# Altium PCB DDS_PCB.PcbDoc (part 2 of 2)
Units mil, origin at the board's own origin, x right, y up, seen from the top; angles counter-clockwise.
Board outline 3998.07 x 3476.44 mil, 8 copper layers (TOP_L1, Plane_L2, Inner_L3, Plane_L4, Plane_L5, Inner_L6, Plane_L7, Bottom Layer_L8), stack 26.8 mil thick; 404 components, 274 nets, 1325 pads, 24 vias.
Unrouted connection lines stored in the file: 923.
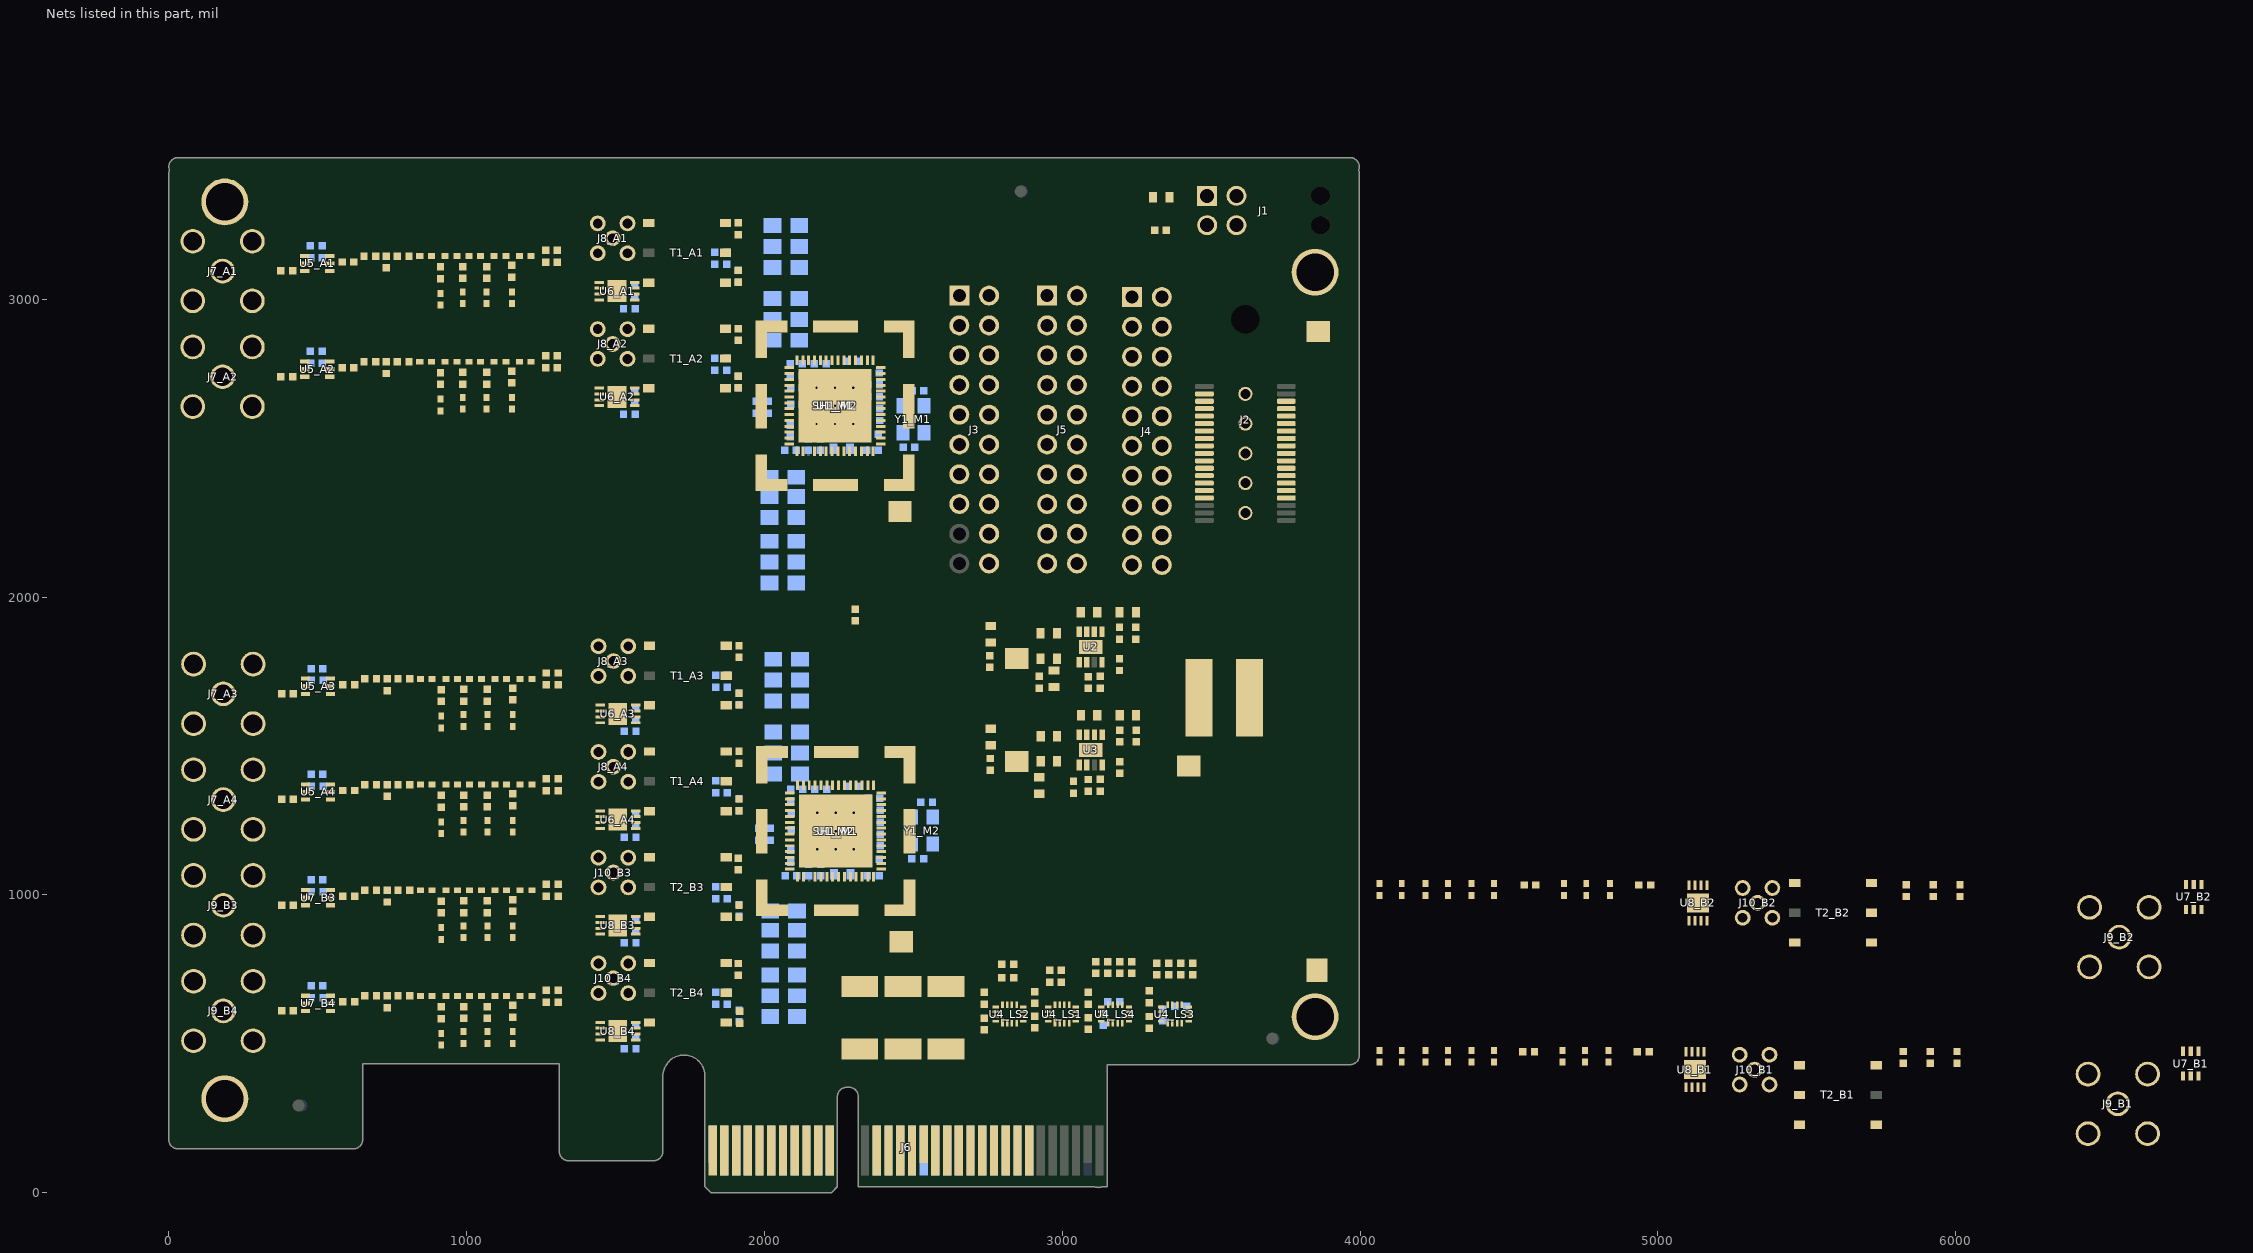
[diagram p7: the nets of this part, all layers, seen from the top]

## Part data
C1_M1 C1_M2: library part "CAP CER 6.8pF 50V NP0 0402", "CAP CER 680PF 50V NP0 0402", Capacitance=680pF, Manufacturer="TDK Corporation", Manufacturer Part Number=C1005C0G1H6R8D, Package / Case="0402 (1005 Metric)", Voltage - Rated=50V
C2_M1 C2_M2 C3_M1 C3_M2: library part "CAP CER 6.8pF 50V NP0 0402", "CAP CER 39PF 50V NP0 0402", Capacitance=39pF, Manufacturer="TDK Corporation", Manufacturer Part Number=C1005C0G1H6R8D, Package / Case="0402 (1005 Metric)", Voltage - Rated=50V
C4_M1 C4_M2 C5_M1 C5_M2 C6_M1 C6_M2 C31_A1 C31_A2 C31_A3 C31_A4 C32_A1 C32_A2 C32_A3 C32_A4 C37_A1 C37_A2 C37_A3 C37_A4 C40_A1 C40_A2 C40_A3 C40_A4 C44_B3 C44_B4 C45_B3 C45_B4 C50_B3 C50_B4 C53_B3 C53_B4: library part "CAP CER 6.8pF 50V NP0 0402", "CAP CER 1uF 25V X5R 0402", Capacitance=1uF, Manufacturer="TDK Corporation", Manufacturer Part Number=C1005C0G1H6R8D, Package / Case="0402 (1005 Metric)", Voltage - Rated=50V
C7_M1 C7_M2 C8_M1 C8_M2 C9_M1 C9_M2 C43_A1 C43_A2 C43_A3 C43_A4 C56_B3 C56_B4: library part "CAP CER 6.8pF 50V NP0 0402", "CAP CER 10uF 10V X5R 0402", Capacitance=10uF, Manufacturer="TDK Corporation", Manufacturer Part Number=C1005C0G1H6R8D, Package / Case="0402 (1005 Metric)", Voltage - Rated=50V
C10_M1 C10_M2 C11_M1 C11_M2 C12_M1 C12_M2 C29_LS1 C29_LS2 C29_LS3 C29_LS4 C30_LS1 C30_LS2 C30_LS3 C30_LS4 C38_A1 C38_A2 C38_A3 C38_A4 C39_A1 C39_A2 C39_A3 C39_A4 C41_A1 C41_A2 C41_A3 C41_A4 C42_A1 C42_A2 C42_A3 C42_A4 C51_B3 C51_B4 C52_B3 C52_B4 C54_B3 C54_B4 C55_B3 C55_B4: library part "CAP CER 6.8pF 50V NP0 0402", "CAP CER 0.1uF 50V NP0 0402", Capacitance=0.1uF, Manufacturer="TDK Corporation", Manufacturer Part Number=C1005C0G1H6R8D, Package / Case="0402 (1005 Metric)", Voltage - Rated=50V
C13 C20 C26: library part "CAP CER 10uF 10V 10% X5R 0603", "CAP CER 10UF 25V 10% X5R 0603", Capacitance=10µF, Manufacturer="TDK Corporation", Manufacturer Part Number=C1608X5R1A106K, Package / Case="0603 (1608 Metric)", Voltage - Rated=10V
C14 C15 C18 C19 C22 C24 C25: library part "CAP CER 12nF 25V 10% X7R 0402", "CAP CER 10nF 25V 10% X5R 0402", Capacitance=10nF, Manufacturer="Murata Electronics North America", Manufacturer Part Number=GRM155R71E123KA61D, Package / Case="0402 (1005 Metric)", Voltage - Rated=25V
C16 C17 C23 C27: library part "CAP CER 10uF 10V 10% X5R 0603", "CAP CER 22UF 16V 10% X5R 0603", Capacitance=22µF, Manufacturer="TDK Corporation", Manufacturer Part Number=C1608X5R1A106K, Package / Case="0603 (1608 Metric)", Voltage - Rated=10V
C21 C28: library part "CAP CER 6.8pF 50V NP0 0402", "CAP CER NA 50V NP0 0402", Manufacturer="TDK Corporation", Manufacturer Part Number=C1005C0G1H6R8D, Package / Case="0402 (1005 Metric)", Voltage - Rated=50V
C33_A1 C33_A2 C33_A3 C33_A4 C46_B3 C46_B4: library part "CAP CER 20pF 50V 5% NP0 0402", "CAP CER 16PF 50V 5% NP0 0402", Capacitance=16pF, Manufacturer="TDK Corporation", Manufacturer Part Number=C1005C0G1H200J, Package / Case="0402 (1005 Metric)", Voltage - Rated=50V
C34_A1 C34_A2 C34_A3 C34_A4 C47_B3 C47_B4: library part "CAP CER 20pF 50V 5% NP0 0402", "CAP CER 11PF 50V 5% NP0 0402", Capacitance=11pF, Manufacturer="TDK Corporation", Manufacturer Part Number=C1005C0G1H200J, Package / Case="0402 (1005 Metric)", Voltage - Rated=50V
C35_A1 C35_A2 C35_A3 C35_A4 C48_B3 C48_B4: library part "CAP CER 20pF 50V 5% NP0 0402", "CAP CER 10PF 50V 5% NP0 0402", Capacitance=10pF, Manufacturer="TDK Corporation", Manufacturer Part Number=C1005C0G1H200J, Package / Case="0402 (1005 Metric)", Voltage - Rated=50V
C36_A1 C36_A2 C36_A3 C36_A4 C49_B3 C49_B4: library part "CAP CER 20pF 50V 5% NP0 0402", "CAP CER 13PF 50V 5% NP0 0402", Capacitance=13pF, Manufacturer="TDK Corporation", Manufacturer Part Number=C1005C0G1H200J, Package / Case="0402 (1005 Metric)", Voltage - Rated=50V
F1 F2 F3: library part 1812L150/24MR, "FUSE PTC 24V 1.5A POLYFUSE 1812", Current - Hold (Ih) (Max)=1.5A, Manufacturer="Littelfuse Inc", Package / Case="1812 (4532 Metric), Concave"
FB1_M1 FB1_M2 FB2 FB3 FB4 FB5: library part BK1608HS600-T, "FERRITE BEAD 220_OHM@100MHz 0603 2A 50mohm_DC", Manufacturer="Taiyo Yuden", Package / Case="0603 (1608 Metric)"
H1 H2 H3 H4: "hole 3mm"
J1: "No Description Available", Mfr_Name="Molex Connector Corporation"
J2: "CONN MICTOR 38POS .025 VERT SMD", Manufacturer="TE Connectivity"
J3 J4 J5: "CONN HEADER 20 TH", Manufacturer="Molex Connector Corporation"
J6: "64 Position Female Connector PCI Expressâ„¢ Gold 0.039 _1.00mm_ Black", Package=None
J7_A1 J7_A2 J7_A3 J7_A4 J9_B1 J9_B2 J9_B3 J9_B4: "No Description Available", Mfr_Name="Samtec Inc"
J8_A1 J8_A2 J8_A3 J8_A4 J10_B1 J10_B2 J10_B3 J10_B4: "MMCX STRAIGHT, THROUGH HOLE JACK- 50 OHM", Package=None
LD1 LD2: "LED 1.6X0.8MM 568NM GRN CLR SMD", Manufacturer="Kingbright Corp", Package / Case="0603 (1608 Metric)"
Lp1: "INDUCTOR 10UH 1.9A 20% SMD", Manufacturer="Taiyo Yuden", Package / Case="Non Standard"
R1_M1 R1_M2: library part "RES 3.09K OHM 1/16W 1% 0402", "RES 6.8K OHM 1/16W 1% 0402", Manufacturer="Stackpole Electronics Inc", Manufacturer Part Number=RMCF0402FT3K09, Package / Case="0402 (1005 Metric)", Power (Watts)="0.063W, 1/16W", Supplier Device Package=0402
R2_M1 R2_M2 R7_M1 R7_M2 R8_M1 R8_M2 R9_M1 R9_M2 R10_M1 R10_M2 R33 R41_A1 R41_A2 R41_A3 R41_A4 R42_A1 R42_A2 R42_A3 R42_A4 R48_B1 R48_B2 R48_B3 R48_B4 R49_B1 R49_B2 R49_B3 R49_B4: library part "RES 100 OHM 1/10W 1% 0402 SMD", "RES 0 OHM 1/10W 1% 0402 SMD", Manufacturer="Panasonic Electronic Components", Manufacturer Part Number=ERJ-2RKF1000X, Package / Case="0402 (1005 Metric)", Supplier Device Package=0402
R3_M1 R3_M2 R4_M1 R4_M2 R5_M1 R5_M2 R6_M1 R6_M2 R11_M1 R11_M2 R12_M1 R12_M2 R13_M1 R13_M2 R14_M1 R14_M2: library part "RES 3.09K OHM 1/16W 1% 0402", "RES 10K OHM 1/16W 1% 0402", Manufacturer="Stackpole Electronics Inc", Manufacturer Part Number=RMCF0402FT3K09, Package / Case="0402 (1005 Metric)", Power (Watts)="0.063W, 1/16W", Supplier Device Package=0402
R15_M1 R15_M2 R16_M1 R16_M2 R17_M1 R17_M2 R18_M1 R18_M2 R19_M1 R19_M2 R20_M1 R20_M2 R21_M1 R21_M2 R22_M1 R22_M2 R23_M1 R23_M2 R24_M1 R24_M2 R25_M1 R25_M2 R26_M1 R26_M2: library part "RES 200 OHM 1/8W 1% 0805 SMD", "RES 0 OHM 1/8W 1% 0805 SMD", Manufacturer="Stackpole Electronics Inc", Manufacturer Part Number=RMCF0805FT200R, Package / Case="0805 (2012 Metric)", Power (Watts)="0.125W, 1/8W", Supplier Device Package=0805
R27 R30: library part "RES 15.4K OHM 1/10W 1% 0402 SMD", "RES 124K OHM 1/10W 1% 0402 SMD", Manufacturer="Panasonic Electronic Components", Manufacturer Part Number=ERJ-2RKF1542X, Package / Case="0402 (1005 Metric)", Power (Watts)="0.1W, 1/10W", Supplier Device Package=0402
R28 R31: library part "RES 3.09K OHM 1/16W 1% 0402", "RES 1K OHM 1/16W 1% 0402", Manufacturer="Stackpole Electronics Inc", Manufacturer Part Number=RMCF0402FT3K09, Package / Case="0402 (1005 Metric)", Power (Watts)="0.063W, 1/16W", Supplier Device Package=0402
R29: library part "RES 15.4K OHM 1/10W 1% 0402 SMD", "RES 39.2K OHM 1/10W 1% 0402 SMD", Manufacturer="Panasonic Electronic Components", Manufacturer Part Number=ERJ-2RKF1542X, Package / Case="0402 (1005 Metric)", Power (Watts)="0.1W, 1/10W", Supplier Device Package=0402
R32 R34_LS1 R34_LS2 R34_LS3 R34_LS4: library part "RES 3.09K OHM 1/16W 1% 0402", "RES 100K OHM 1/16W 1% 0402", Manufacturer="Stackpole Electronics Inc", Manufacturer Part Number=RMCF0402FT3K09, Package / Case="0402 (1005 Metric)", Power (Watts)="0.063W, 1/16W", Supplier Device Package=0402
R35_LS1 R35_LS2 R35_LS3 R35_LS4: library part "RES 3.09K OHM 1/16W 1% 0402", "RES 3.09K OHM 1/16W 1% 0402", Manufacturer="Stackpole Electronics Inc", Manufacturer Part Number=RMCF0402FT3K09, Package / Case="0402 (1005 Metric)", Power (Watts)="0.063W, 1/16W", Supplier Device Package=0402
R36_A1 R36_A2 R36_A3 R36_A4 R37_A1 R37_A2 R37_A3 R37_A4 R43_B1 R43_B2 R43_B3 R43_B4 R44_B1 R44_B2 R44_B3 R44_B4: library part "RES 100 OHM 1/10W 1% 0402 SMD", "RES 34.8 OHM 1/10W 1% 0402 SMD", Manufacturer="Panasonic Electronic Components", Manufacturer Part Number=ERJ-2RKF1000X, Package / Case="0402 (1005 Metric)", Supplier Device Package=0402
R38_A1 R38_A2 R38_A3 R38_A4 R45_B1 R45_B2 R45_B3 R45_B4: library part "RES 100 OHM 1/10W 1% 0402 SMD", "RES 18.2 OHM 1/10W 1% 0402 SMD", Manufacturer="Panasonic Electronic Components", Manufacturer Part Number=ERJ-2RKF1000X, Package / Case="0402 (1005 Metric)", Supplier Device Package=0402
R39_A1 R39_A2 R39_A3 R39_A4 R40_A1 R40_A2 R40_A3 R40_A4 R46_B3 R46_B4 R47_B3 R47_B4: library part "RES 100 OHM 1/10W 1% 0402 SMD", "RES 49.9 OHM 1/10W 1% 0402 SMD", Manufacturer="Panasonic Electronic Components", Manufacturer Part Number=ERJ-2RKF1000X, Package / Case="0402 (1005 Metric)", Supplier Device Package=0402
SH1_M1 SH1_M2: "RF SHIELD 0.5\" X 0.538\" SMD", Manufacturer="Leader Tech Inc.", Manufacturer_Part_Number=SMS-201F
T1_A1 T1_A2 T1_A3 T1_A4 T2_B1 T2_B2 T2_B3 T2_B4: "No Description Available", Mfr_Name="Mini Circuits"
TP1 TP2 TP3 TP4 TP5 TP6: library part "TP mini_2", "TP PC MINIATURE SMT", Manufacturer="Keystone Electronics", Manufacturer Part Number=5015
TP7: library part "TP mini_1", "TP PC MINIATURE SMT", Manufacturer="Keystone Electronics", Manufacturer Part Number=5015
U1_M1 U1_M2 U6_A1 U6_A2 U6_A3 U6_A4 U8_B1 U8_B2 U8_B3 U8_B4: "No Description Available", Mfr_Name="Analog Devices Inc"
U2 U3: "No Description Available", Mfr_Name=Delta
U5_A1 U5_A2 U5_A3 U5_A4 U7_B1 U7_B2 U7_B3 U7_B4: "No Description Available", Mfr_Name=NXP
Y1_M1 Y1_M2: "No Description Available", Mfr_Name="ECS International"

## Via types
v1: diameter 16, hole 8, TOP_L1 to Bottom Layer_L8, tented both sides, 18 vias
v2: diameter 25.59, hole 11.81, TOP_L1 to Bottom Layer_L8, tented both sides, 6 vias

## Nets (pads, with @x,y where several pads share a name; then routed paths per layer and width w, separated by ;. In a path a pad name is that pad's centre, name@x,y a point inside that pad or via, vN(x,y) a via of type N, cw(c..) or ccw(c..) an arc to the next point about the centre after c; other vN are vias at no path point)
1.8V: C23.2 C27.2 FB5.1 R30.2 U3.4 U3.5
1_8V: F2.1 J6.B5 J6.B6 J6.B7 J6.B8
3.3V: C16.2 C17.2 FB3.1 R27.2 U2.4 U2.5
3_3V: F1.1 J6.B1 J6.B2 J6.B3 J6.B4
12_V: F3.2 J6.A1 J6.A2 J6.A3 J6.A4
12v_1: C19.2 C20.2 FB2.2 U2.1 U2.2
12v_2: C25.2 C26.2 FB4.2 U3.1 U3.2
12v_in: C13.2 C14.2 J1.1 J1.2 Lp1.1
AVDD0_M1: C41_A1.2 C42_A1.2 C43_A1.2 R18_M1.2 R22_M1.2 R26_M1.2 R39_A1.2 R40_A1.1 T1_A1.2
AVDD0_M2: C41_A3.2 C42_A3.2 C43_A3.2 R18_M2.2 R22_M2.2 R26_M2.2 R39_A3.2 R40_A3.1 T1_A3.2
AVDD1_M1: C41_A2.2 C42_A2.2 C43_A2.2 R17_M1.2 R18_M1.1 R21_M1.2 R22_M1.1 R25_M1.2 R26_M1.1 R39_A2.2 R40_A2.1 T1_A2.2
AVDD1_M2: C41_A4.2 C42_A4.2 C43_A4.2 R17_M2.2 R18_M2.1 R21_M2.2 R22_M2.1 R25_M2.2 R26_M2.1 R39_A4.2 R40_A4.1 T1_A4.2
AVDD2_M1: R16_M1.2 R17_M1.1 R20_M1.2 R21_M1.1 R24_M1.2 R25_M1.1
AVDD2_M2: R16_M2.2 R17_M2.1 R20_M2.2 R21_M2.1 R24_M2.2 R25_M2.1
AVDD3_M1: R15_M1.2 R16_M1.1 R19_M1.2 R20_M1.1 R23_M1.2 R24_M1.1
AVDD3_M2: R15_M2.2 R16_M2.1 R19_M2.2 R20_M2.1 R23_M2.2 R24_M2.1
AVDD_B1: T2_B1.2
AVDD_B2: T2_B2.2
AVDD_B3: C54_B3.2 C55_B3.2 C56_B3.2 R46_B3.2 R47_B3.1 T2_B3.2
AVDD_B4: C54_B4.2 C55_B4.2 C56_B4.2 R46_B4.2 R47_B4.1 T2_B4.2
CH__N0_M1: T2_B1.1
CH__N0_M2: R47_B3.2 T2_B3.1
CH__N1_M1: T2_B2.1
CH__N1_M2: R47_B4.2 T2_B4.1
CH__N2_M1: U1_M1.9
CH__N2_M2: U1_M2.9
CH__N3_M1: U1_M1.14
CH__N3_M2: U1_M2.14
CH__P0_M1: T2_B1.3
CH__P0_M2: R46_B3.1 T2_B3.3
CH__P1_M1: T2_B2.3
CH__P1_M2: R46_B4.1 T2_B4.3
CH__P2_M1: U1_M1.8
CH__P2_M2: U1_M2.8
CH__P3_M1: U1_M1.13
CH__P3_M2: U1_M2.13
CH_N0_M1: R40_A1.2 T1_A1.3 U1_M1.29
CH_N0_M2: R40_A3.2 T1_A3.3 U1_M2.29
CH_N1_M1: R40_A2.2 T1_A2.3 U1_M1.35
CH_N1_M2: R40_A4.2 T1_A4.3 U1_M2.35
CH_P0_M1: R39_A1.1 T1_A1.1 U1_M1.30
CH_P0_M2: R39_A3.1 T1_A3.1 U1_M2.30
CH_P1_M1: R39_A2.1 T1_A2.1 U1_M1.36
CH_P1_M2: R39_A4.1 T1_A4.1 U1_M2.36
CLK_sel_M1: R8_M1.1 R10_M1.2 U1_M1.24
CLK_sel_M2: R8_M2.1 R10_M2.2 U1_M2.24
contr0_M1: J2.26 J3.1 J6.B13 U6_A1.2
contr0_M2: J2.25 J3.9 J6.A13 U6_A3.2
contr1_M1: J2.28 J3.3 J6.B14 U6_A2.2
contr1_M2: J2.27 J3.11 J6.A14 U6_A4.2
contr2_M1: J2.30 J3.5 J6.B15
contr2_M2: J2.29 J3.13 J6.A15
contr3_M1: J2.32 J3.7 J6.B16
contr3_M2: J2.31 J3.15 J6.A16
contr_B1: U8_B1.2
contr_B2: U8_B2.2
contr_B3: U8_B3.2
contr_B4: U8_B4.2
CSn: U1_M1.47 U4_LS2.12
CSn_2: U1_M2.47 U4_LS1.12
CSn_2_L: J2.7 J5.3 J6.A18 U4_LS1.1
CSn_L: J2.8 J4.3 J6.B18 U4_LS2.1
DAC_O_A1: T1_A1.6 U6_A1.4
DAC_O_A2: T1_A2.6 U6_A2.4
DAC_O_A3: T1_A3.6 U6_A3.4
DAC_O_A4: T1_A4.6 U6_A4.4
DAC_O_B1: T2_B1.4 U8_B1.4
DAC_O_B2: T2_B2.4 U8_B2.4
DAC_O_B3: T2_B3.4 U8_B3.4
DAC_O_B4: T2_B4.4 U8_B4.4
DIR_LS1: J2.21 J5.17 J6.A25 R34_LS1.1 R34_LS4.1 R35_LS1.2 R35_LS4.2 U4_LS1.5 U4_LS1.6 U4_LS1.15 U4_LS1.16 U4_LS4.5 U4_LS4.6 U4_LS4.15 U4_LS4.16
DIR_LS2: J2.22 J4.17 J6.B25 R34_LS2.1 R34_LS3.1 R35_LS2.2 R35_LS3.2 U4_LS2.5 U4_LS2.6 U4_LS2.15 U4_LS2.16 U4_LS3.5 U4_LS3.6 U4_LS3.15 U4_LS3.16
FB_1.8: R30.1 R32.2 U3.6
FB_3.3: R27.1 R29.2 U2.6
GND: C2_M1.2 C2_M2.2 C3_M1.1 C3_M2.1 C4_M1.1 C4_M2.1 C5_M1.1 C5_M2.1 C6_M1.1 C6_M2.1 C7_M1.1 C7_M2.1 C8_M1.1 C8_M2.1 C9_M1.1 C9_M2.1 C10_M1.1 C10_M2.1 C11_M1.1 C11_M2.1 C12_M1.1 C12_M2.1 C13.1 C14.1 C15.1 C16.1 C17.1 C18.1 C19.1 C20.1 C21.1 C22.1 C23.1 C24.1 C25.1 C26.1 C27.1 C28.1 C29_LS1.1 C29_LS2.1 C29_LS3.1 C29_LS4.1 C30_LS1.1 C30_LS2.1 C30_LS3.1 C30_LS4.1 C37_A1.1 C37_A2.1 C37_A3.1 C37_A4.1 C38_A1.1 C38_A2.1 C38_A3.1 C38_A4.1 C39_A1.1 C39_A2.1 C39_A3.1 C39_A4.1 C40_A1.1 C40_A2.1 C40_A3.1 C40_A4.1 C41_A1.1 C41_A2.1 C41_A3.1 C41_A4.1 C42_A1.1 C42_A2.1 C42_A3.1 C42_A4.1 C43_A1.1 C43_A2.1 C43_A3.1 C43_A4.1 C50_B3.1 C50_B4.1 C51_B3.1 C51_B4.1 C52_B3.1 C52_B4.1 C53_B3.1 C53_B4.1 C54_B3.1 C54_B4.1 C55_B3.1 C55_B4.1 C56_B3.1 C56_B4.1 H1.1 H2.1 H3.1 H4.1 J1.3 J1.4 J2.3 J2.39 J2.40 J2.41 J2.42 J2.43 J3.2 J3.4 J3.6 J3.8 J3.10 J3.12 J3.14 J3.16 J3.18 J3.20 J4.2 J4.4 J4.6 J4.8 J4.10 J4.12 J4.14 J4.16 J4.18 J4.20 J5.2 J5.4 J5.6 J5.8 J5.10 J5.12 J5.14 J5.16 J5.18 J5.20 J6.A5 J6.A6 J6.A7 J6.A8 J6.A9 J6.A10 J6.A11 J6.B9 J6.B10 J6.B11 J7_A1.2 J7_A1.3 J7_A1.4 J7_A1.5 J7_A2.2 J7_A2.3 J7_A2.4 J7_A2.5 J7_A3.2 J7_A3.3 J7_A3.4 J7_A3.5 J7_A4.2 J7_A4.3 J7_A4.4 J7_A4.5 J8_A1.S1 J8_A1.S2 J8_A1.S3 J8_A1.S4 J8_A2.S1 J8_A2.S2 J8_A2.S3 J8_A2.S4 J8_A3.S1 J8_A3.S2 J8_A3.S3 J8_A3.S4 J8_A4.S1 J8_A4.S2 J8_A4.S3 J8_A4.S4 J9_B1.2 J9_B1.3 J9_B1.4 J9_B1.5 J9_B2.2 J9_B2.3 J9_B2.4 J9_B2.5 J9_B3.2 J9_B3.3 J9_B3.4 J9_B3.5 J9_B4.2 J9_B4.3 J9_B4.4 J9_B4.5 J10_B1.S1 J10_B1.S2 J10_B1.S3 J10_B1.S4 J10_B2.S1 J10_B2.S2 J10_B2.S3 J10_B2.S4 J10_B3.S1 J10_B3.S2 J10_B3.S3 J10_B3.S4 J10_B4.S1 J10_B4.S2 J10_B4.S3 J10_B4.S4 L6_A1.2 L6_A2.2 L6_A3.2 L6_A4.2 L7_A1.2 L7_A2.2 L7_A3.2 L7_A4.2 L8_A1.2 L8_A2.2 L8_A3.2 L8_A4.2 L9_A1.2 L9_A2.2 L9_A3.2 L9_A4.2 L15_B1.2 L15_B2.2 L15_B3.2 L15_B4.2 L16_B1.2 L16_B2.2 L16_B3.2 L16_B4.2 L17_B1.2 L17_B2.2 L17_B3.2 L17_B4.2 L18_B1.2 L18_B2.2 L18_B3.2 L18_B4.2 LD1.2 LD2.2 R1_M1.1 R1_M2.1 R3_M1.1 R3_M2.1 R4_M1.1 R4_M2.1 R5_M1.1 R5_M2.1 R6_M1.1 R6_M2.1 R9_M1.1 R9_M2.1 R10_M1.1 R10_M2.1 R11_M1.1 R11_M2.1 R12_M1.1 R12_M2.1 R13_M1.1 R13_M2.1 R14_M1.1 R14_M2.1 R29.1 R32.1 R35_LS1.1 R35_LS2.1 R35_LS3.1 R35_LS4.1 R38_A1.2 R38_A2.2 R38_A3.2 R38_A4.2 R45_B1.2 R45_B2.2 R45_B3.2 R45_B4.2 SH1_M1.1 SH1_M2.1 T1_A1.4 T1_A2.4 T1_A3.4 T1_A4.4 T2_B1.6 T2_B2.6 T2_B3.6 T2_B4.6 TP6.1 TP7.1 U1_M1.6 U1_M1.10 U1_M1.12 U1_M1.16 U1_M1.18 U1_M1.20 U1_M1.25 U1_M1.28 U1_M1.32 U1_M1.34 U1_M1.38 U1_M1.44 U1_M1.56 U1_M1.57 U1_M2.6 U1_M2.10 U1_M2.12 U1_M2.16 U1_M2.18 U1_M2.20 U1_M2.25 U1_M2.28 U1_M2.32 U1_M2.34 U1_M2.38 U1_M2.44 U1_M2.56 U1_M2.57 U2.3 U2.9 U3.3 U3.9 U4_LS1.7 U4_LS1.8 U4_LS2.7 U4_LS2.8 U4_LS3.7 U4_LS3.8 U4_LS4.7 U4_LS4.8 U5_A1.2 U5_A1.4 U5_A1.5 U5_A2.2 U5_A2.4 U5_A2.5 U5_A3.2 U5_A3.4 U5_A3.5 U5_A4.2 U5_A4.4 U5_A4.5 U6_A1.3 U6_A1.5 U6_A1.6 U6_A1.7 U6_A1.9 U6_A2.3 U6_A2.5 U6_A2.6 U6_A2.7 U6_A2.9 U6_A3.3 U6_A3.5 U6_A3.6 U6_A3.7 U6_A3.9 U6_A4.3 U6_A4.5 U6_A4.6 U6_A4.7 U6_A4.9 U7_B1.2 U7_B1.4 U7_B1.5 U7_B2.2 U7_B2.4 U7_B2.5 U7_B3.2 U7_B3.4 U7_B3.5 U7_B4.2 U7_B4.4 U7_B4.5 U8_B1.3 U8_B1.5 U8_B1.6 U8_B1.7 U8_B1.9 U8_B2.3 U8_B2.5 U8_B2.6 U8_B2.7 U8_B2.9 U8_B3.3 U8_B3.5 U8_B3.6 U8_B3.7 U8_B3.9 U8_B4.3 U8_B4.5 U8_B4.6 U8_B4.7 U8_B4.9 Y1_M1.2 Y1_M1.4 Y1_M2.2 Y1_M2.4
  other v1: 2176.9,1153.11 2238.9,1153.11 2299.9,1153.11 2176.9,1214.11 2238.9,1214.11 2299.9,1214.11 2176.9,1275.11 2238.9,1275.11 2299.9,1275.11 2174.85,2581.52 2236.85,2581.52 2297.85,2581.52 2174.85,2642.52 2236.85,2642.52 2297.85,2642.52 2174.85,2703.52 2236.85,2703.52 2297.85,2703.52
IO_UPDATE: U1_M1.46 U4_LS2.10
IO_UPDATE_2: U1_M2.46 U4_LS1.10
IO_UPDATE_2_L: J2.9 J5.1 J6.A19 U4_LS1.3
IO_UPDATE_L: J2.10 J4.1 J6.B19 U4_LS2.3
MASTER_RESET: U4_LS2.9
MASTER_RESET_2: U4_LS1.9
MASTER_RESET_2_L: J2.11 J5.7 J6.A20 U4_LS1.4
MASTER_RESET_L: J2.12 J4.7 J6.B20 U4_LS2.4
NetC1_M1_2: C1_M1.2 R2_M1.2
NetC1_M2_2: C1_M2.2 R2_M2.2
NetC21_2: C21.2 U2.8
NetC28_2: C28.2 U3.8
NetC44_B1_1: J9_B1.1
NetC44_B2_1: J9_B2.1
NetC44_B3_1: C44_B3.1 J9_B3.1
NetC44_B4_1: C44_B4.1 J9_B4.1
NetC46_B1_1: L10_B1.1 L11_B1.2
NetC46_B1_2: L15_B1.1
NetC46_B2_1: L10_B2.1 L11_B2.2
NetC46_B2_2: L15_B2.1
NetC46_B3_1: C46_B3.1 L10_B3.1 L11_B3.2
NetC46_B3_2: C46_B3.2 L15_B3.1
NetC46_B4_1: C46_B4.1 L10_B4.1 L11_B4.2
NetC46_B4_2: C46_B4.2 L15_B4.1
NetC47_B1_1: L10_B1.2 L12_B1.1
NetC47_B1_2: L16_B1.1
NetC47_B2_1: L10_B2.2 L12_B2.1
NetC47_B2_2: L16_B2.1
NetC47_B3_1: C47_B3.1 L10_B3.2 L12_B3.1
NetC47_B3_2: C47_B3.2 L16_B3.1
NetC47_B4_1: C47_B4.1 L10_B4.2 L12_B4.1
NetC47_B4_2: C47_B4.2 L16_B4.1
NetC48_B1_1: L12_B1.2 L13_B1.1
NetC48_B1_2: L17_B1.1
NetC48_B2_1: L12_B2.2 L13_B2.1
NetC48_B2_2: L17_B2.1
NetC48_B3_1: C48_B3.1 L12_B3.2 L13_B3.1
NetC48_B3_2: C48_B3.2 L17_B3.1
NetC48_B4_1: C48_B4.1 L12_B4.2 L13_B4.1
NetC48_B4_2: C48_B4.2 L17_B4.1
NetC49_B1_1: L13_B1.2 L14_B1.1
NetC49_B1_2: L18_B1.1
NetC49_B2_1: L13_B2.2 L14_B2.1
NetC49_B2_2: L18_B2.1
NetC49_B3_1: C49_B3.1 L13_B3.2 L14_B3.1
NetC49_B3_2: C49_B3.2 L18_B3.1
NetC49_B4_1: C49_B4.1 L13_B4.2 L14_B4.1
NetC49_B4_2: C49_B4.2 L18_B4.1
NetJ8_A1_1: J8_A1.1 R41_A1.1
NetJ8_A2_1: J8_A2.1 R41_A2.1
NetJ8_A3_1: J8_A3.1 R41_A3.1
NetJ8_A4_1: J8_A4.1 R41_A4.1
NetJ10_B1_1: J10_B1.1 R48_B1.1
NetJ10_B2_1: J10_B2.1 R48_B2.1
NetJ10_B3_1: J10_B3.1 R48_B3.1
NetJ10_B4_1: J10_B4.1 R48_B4.1
NetL11_B1_1: L11_B1.1 R49_B1.2
NetL11_B2_1: L11_B2.1 R49_B2.2
NetL11_B3_1: L11_B3.1 R49_B3.2
NetL11_B4_1: L11_B4.1 R49_B4.2
NetLD1_1: LD1.1 R28.1
NetLD2_1: LD2.1 R31.1
NetR1_M1_2: R1_M1.2 U1_M1.17
NetR1_M2_2: R1_M2.2 U1_M2.17
NetR2_M1_1: R2_M1.1 U1_M1.27
NetR2_M2_1: R2_M2.1 U1_M2.27
NetR43_B1_1: R43_B1.1 R44_B1.2 R45_B1.1
NetR43_B2_1: R43_B2.1 R44_B2.2 R45_B2.1
NetR43_B3_1: R43_B3.1 R44_B3.2 R45_B3.1
NetR43_B4_1: R43_B4.1 R44_B4.2 R45_B4.1
OUT_A1: L5_A1.2 R37_A1.1
OUT_A2: L5_A2.2 R37_A2.1
OUT_A3: L5_A3.2 R37_A3.1
OUT_A4: L5_A4.2 R37_A4.1
OUT_B1: L14_B1.2 R44_B1.1
OUT_B2: L14_B2.2 R44_B2.1
OUT_B3: L14_B3.2 R44_B3.1
OUT_B4: L14_B4.2 R44_B4.1
P0_M1: R11_M1.2 U1_M1.40
P0_M2: R11_M2.2 U1_M2.40
P1.8V_ana_M1: C1_M1.1 C6_M1.2 C9_M1.2 C12_M1.2 FB1_M1.2 R8_M1.2 R15_M1.1 R19_M1.1 R23_M1.1 U1_M1.5 U1_M1.7 U1_M1.11 U1_M1.15 U1_M1.19 U1_M1.21 U1_M1.26 U1_M1.31 U1_M1.33 U1_M1.37 U1_M1.39
P1.8V_ana_M2: C1_M2.1 C6_M2.2 C9_M2.2 C12_M2.2 FB1_M2.2 R8_M2.2 R15_M2.1 R19_M2.1 R23_M2.1 U1_M2.5 U1_M2.7 U1_M2.11 U1_M2.15 U1_M2.19 U1_M2.21 U1_M2.26 U1_M2.31 U1_M2.33 U1_M2.37 U1_M2.39
P1_M1: R12_M1.2 U1_M1.41
P1_M2: R12_M2.2 U1_M2.41
P2_M1: R13_M1.2 U1_M1.42
P2_M2: R13_M2.2 U1_M2.42
P3_M1: R14_M1.2 U1_M1.43
P3_M2: R14_M2.2 U1_M2.43
P12V: C15.2 C22.2 F3.1 FB2.1 FB4.1 Lp1.2 TP1.1
PWR_DWN_CTR_M1: R7_M1.1 R9_M1.2 U1_M1.4
PWR_DWN_CTR_M2: R7_M2.1 R9_M2.2 U1_M2.4
REF_CLK_M1_N: C3_M1.2 U1_M1.22 Y1_M1.1
REF_CLK_M1_P: C2_M1.1 U1_M1.23 Y1_M1.3
REF_CLK_M2_N: C3_M2.2 U1_M2.22 Y1_M2.1
REF_CLK_M2_P: C2_M2.1 U1_M2.23 Y1_M2.3
RF_1_A1: L2_A1.1 R42_A1.2
RF_1_A2: L2_A2.1 R42_A2.2
RF_1_A3: L2_A3.1 R42_A3.2
RF_1_A4: L2_A4.1 R42_A4.2
RF_2_A1: C33_A1.1 L1_A1.1 L2_A1.2
RF_2_A2: C33_A2.1 L1_A2.1 L2_A2.2
RF_2_A3: C33_A3.1 L1_A3.1 L2_A3.2
RF_2_A4: C33_A4.1 L1_A4.1 L2_A4.2
RF_3_A1: C34_A1.1 L1_A1.2 L3_A1.1
RF_3_A2: C34_A2.1 L1_A2.2 L3_A2.1
RF_3_A3: C34_A3.1 L1_A3.2 L3_A3.1
RF_3_A4: C34_A4.1 L1_A4.2 L3_A4.1
RF_4_A1: C35_A1.1 L3_A1.2 L4_A1.1
RF_4_A2: C35_A2.1 L3_A2.2 L4_A2.1
RF_4_A3: C35_A3.1 L3_A3.2 L4_A3.1
RF_4_A4: C35_A4.1 L3_A4.2 L4_A4.1
RF_5_A1: C36_A1.1 L4_A1.2 L5_A1.1
RF_5_A2: C36_A2.1 L4_A2.2 L5_A2.1
RF_5_A3: C36_A3.1 L4_A3.2 L5_A3.1
RF_5_A4: C36_A4.1 L4_A4.2 L5_A4.1
RF_6_A1: C33_A1.2 L9_A1.1
RF_6_A2: C33_A2.2 L9_A2.1
RF_6_A3: C33_A3.2 L9_A3.1
RF_6_A4: C33_A4.2 L9_A4.1
RF_7_A1: C34_A1.2 L6_A1.1
RF_7_A2: C34_A2.2 L6_A2.1
RF_7_A3: C34_A3.2 L6_A3.1
RF_7_A4: C34_A4.2 L6_A4.1
RF_8_A1: C35_A1.2 L7_A1.1
RF_8_A2: C35_A2.2 L7_A2.1
RF_8_A3: C35_A3.2 L7_A3.1
RF_8_A4: C35_A4.2 L7_A4.1
RF_9_A1: C36_A1.2 L8_A1.1
RF_9_A2: C36_A2.2 L8_A2.1
RF_9_A3: C36_A3.2 L8_A3.1
RF_9_A4: C36_A4.2 L8_A4.1
RF_10_A1: R36_A1.1 R37_A1.2 R38_A1.1
RF_10_A2: R36_A2.1 R37_A2.2 R38_A2.1
RF_10_A3: R36_A3.1 R37_A3.2 R38_A3.1
RF_10_A4: R36_A4.1 R37_A4.2 R38_A4.1
RF_i_A1: R41_A1.2 R42_A1.1 U6_A1.8
RF_i_A2: R41_A2.2 R42_A2.1 U6_A2.8
RF_i_A3: R41_A3.2 R42_A3.1 U6_A3.8
RF_i_A4: R41_A4.2 R42_A4.1 U6_A4.8
RF_i_B1: R48_B1.2 R49_B1.1 U8_B1.8
RF_i_B2: R48_B2.2 R49_B2.1 U8_B2.8
RF_i_B3: R48_B3.2 R49_B3.1 U8_B3.8
RF_i_B4: R48_B4.2 R49_B4.1 U8_B4.8
RF_o_A1: C32_A1.2 R36_A1.2
RF_o_A2: C32_A2.2 R36_A2.2
RF_o_A3: C32_A3.2 R36_A3.2
RF_o_A4: C32_A4.2 R36_A4.2
RF_o_B1: R43_B1.2
RF_o_B2: R43_B2.2
RF_o_B3: C45_B3.2 R43_B3.2
RF_o_B4: C45_B4.2 R43_B4.2
RFi_A1: C32_A1.1 U5_A1.6
RFi_A2: C32_A2.1 U5_A2.6
RFi_A3: C32_A3.1 U5_A3.6
RFi_A4: C32_A4.1 U5_A4.6
RFi_B1: U7_B1.6
RFi_B2: U7_B2.6
RFi_B3: C45_B3.1 U7_B3.6
RFi_B4: C45_B4.1 U7_B4.6
RFo_A1: C31_A1.2 U5_A1.3
RFo_A2: C31_A2.2 U5_A2.3
RFo_A3: C31_A3.2 U5_A3.3
RFo_A4: C31_A4.2 U5_A4.3
RFo_B1: U7_B1.3
RFo_B2: U7_B2.3
RFo_B3: C44_B3.2 U7_B3.3
RFo_B4: C44_B4.2 U7_B4.3
RFout_A1: C31_A1.1 J7_A1.1
RFout_A2: C31_A2.1 J7_A2.1
RFout_A3: C31_A3.1 J7_A3.1
RFout_A4: C31_A4.1 J7_A4.1
SCLK: U1_M1.48 U4_LS2.11
SCLK_2: U1_M2.48 U4_LS1.11
SCLK_2_L: J2.5 J5.5 J6.A17 U4_LS1.2
SCLK_L: J2.6 J4.5 J6.B17 U4_LS2.2
SDIO_0: R3_M1.2 U1_M1.50 U4_LS3.12
SDIO_0_2: R3_M2.2 U1_M2.50 U4_LS4.12
SDIO_0_2_L: J2.19 J5.15 J6.A24 U4_LS4.1
SDIO_0_L: J2.20 J4.15 J6.B24 U4_LS3.1
SDIO_1: R4_M1.2 U1_M1.51 U4_LS3.11
SDIO_1_2: R4_M2.2 U1_M2.51 U4_LS4.11
SDIO_1_2_L: J2.17 J5.13 J6.A23 U4_LS4.2
SDIO_1_L: J2.18 J4.13 J6.B23 U4_LS3.2
SDIO_2: R5_M1.2 U1_M1.52 U4_LS3.10
SDIO_2_2: R5_M2.2 U1_M2.52 U4_LS4.10
SDIO_2_2_L: J2.15 J5.11 J6.A22 U4_LS4.3
SDIO_2_L: J2.16 J4.11 J6.B22 U4_LS3.3
SDIO_3: R6_M1.2 U1_M1.53 U4_LS3.9
SDIO_3_2: R6_M2.2 U1_M2.53 U4_LS4.9
SDIO_3_2_L: J2.13 J5.9 J6.A21 U4_LS4.4
SDIO_3_L: J2.14 J4.9 J6.B21 U4_LS3.4
SYNC_CLK: J2.24 J4.19 J6.B26 U1_M1.54
SYNC_CLK_2: J2.23 J5.19 J6.A26 U1_M2.54
SYNC_IN_2: R33.1 U1_M2.1
SYNC_IN_M1: TP4.1 U1_M1.1
SYNC_OUT: R33.2 U1_M1.2
SYNC_OUT_M2: TP5.1 U1_M2.2
VccA_LS1: C5_M1.2 C5_M2.2 C8_M1.2 C8_M2.2 C11_M1.2 C11_M2.2 C24.2 C29_LS1.2 C29_LS2.2 C29_LS3.2 C29_LS4.2 C39_A1.2 C39_A2.2 C39_A3.2 C39_A4.2 C40_A1.2 C40_A2.2 C40_A3.2 C40_A4.2 C52_B3.2 C52_B4.2 C53_B3.2 C53_B4.2 F2.2 FB1_M1.1 FB1_M2.1 FB5.2 R31.2 R34_LS1.2 R34_LS2.2 R34_LS3.2 R34_LS4.2 TP3.1 U1_M1.45 U1_M1.55 U1_M2.45 U1_M2.55 U4_LS1.14 U4_LS2.14 U4_LS3.14 U4_LS4.14 U6_A1.1 U6_A2.1 U6_A3.1 U6_A4.1 U8_B1.1 U8_B2.1 U8_B3.1 U8_B4.1
VccB_LS1: C4_M1.2 C4_M2.2 C7_M1.2 C7_M2.2 C10_M1.2 C10_M2.2 C18.2 C30_LS1.2 C30_LS2.2 C30_LS3.2 C30_LS4.2 C37_A1.2 C37_A2.2 C37_A3.2 C37_A4.2 C38_A1.2 C38_A2.2 C38_A3.2 C38_A4.2 C50_B3.2 C50_B4.2 C51_B3.2 C51_B4.2 F1.2 FB3.2 R7_M1.2 R7_M2.2 R28.2 TP2.1 U1_M1.49 U1_M2.49 U4_LS1.13 U4_LS2.13 U4_LS3.13 U4_LS4.13 U5_A1.1 U5_A2.1 U5_A3.1 U5_A4.1 U7_B1.1 U7_B2.1 U7_B3.1 U7_B4.1
pads on no net: FID1.1 FID2.1 FID3.1 FID4.1 FID5.1 FID6.1 J1.5 J1.6 J2.0 J2.1 J2.2 J2.4 J2.33 J2.34 J2.35 J2.36 J2.37 J2.38 J3.17 J3.19 J6.A12 J6.A27 J6.A28 J6.A29 J6.A30 J6.A31 J6.A32 J6.B12 J6.B27 J6.B28 J6.B29 J6.B30 J6.B31 J6.B32 T1_A1.5 T1_A2.5 T1_A3.5 T1_A4.5 T2_B1.5 T2_B2.5 T2_B3.5 T2_B4.5 U1_M1.3 U1_M2.3 U2.7 U3.7
copper on no net: | length 893.1
  TOP_L1 w9.84: 678.74,3758.3 702.36,3758.3 ; 702.36,3600.04 v2(761.42,3600.04) ; 702.36,3636.26 702.36,3678.78 ; 702.36,3715 702.36,3758.3 ; 725.2,3758.3 702.36,3758.3 ; 761.42,3758.3 785.04,3758.3 ; v2@765.35,3600.04 v2(761.42,3600.04) ; 785.04,3636.26 785.04,3678.78 ; 785.04,3715 785.04,3758.3 ; 807.87,3758.3 785.04,3758.3 ; 844.09,3758.3 867.72,3758.3 ; v2@848.03,3600.04 v2(844.09,3600.04) ; 867.72,3636.26 867.72,3678.78 ; 867.72,3715 867.72,3758.3 ; 891.34,3758.3 867.72,3758.3 ; 927.56,3758.3 950.39,3758.3 ; 950.39,3600.04 v2(926.77,3600.04) 867.72,3600.04 v2(844.09,3600.04) ; 950.39,3636.26 950.39,3678.78 ; 950.39,3715 950.39,3758.3 ; 974.02,3758.3 950.39,3758.3 ; v2(761.42,3600.04) 785.04,3600.04 v2(844.09,3600.04)
  Bottom Layer_L8 w9.84: v2(725.98,3600.82) 726.77,3600.04 v2(761.42,3600.04) ; v2(808.66,3600.82) 809.45,3600.04 v2(844.09,3600.04) ; v2(891.34,3600.82) 895.28,3600.82 896.06,3600.04 v2(926.77,3600.04)

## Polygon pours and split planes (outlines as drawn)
GND on Plane_L2 (split plane): 245 vertices, not listed, extent 19.5,19.43 3977.49,3455.72
GND on Plane_L4 (split plane): 245 vertices, not listed, extent 19.5,19.43 3977.49,3455.72
GND on Plane_L5 (split plane): 245 vertices, not listed, extent 19.5,19.43 3977.49,3455.72
GND on Plane_L7 (split plane): 245 vertices, not listed, extent 19.5,19.43 3977.49,3455.72

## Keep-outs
Keep-Out Layer:
  lines w60: 30.02,3422.53 30.02,177.53 619.57,177.53 ccw(c619.57,178.05) 620.08,178.05 620.08,427.88 ; 30.02,3445.25 3967.02,3445.25 ; 617.6,771.62 cw(c652.3,771.62) 652.3,806.31 1339.01,806.31 ; 1341.49,462.57 1341.49,138.28 ccw(c1342.01,138.28) 1342.01,137.77 1656.97,137.77 ccw(c1656.97,138.28) 1657.48,138.28 1657.48,392.09 ; 3120.65,47.61 3120.65,460.4 3967.02,460.4 3967.02,3422.53

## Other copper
Inner_L3:
  pour cut-out: 619.69,3797.67 619.69,3616.57 1033.07,3616.57 1033.07,3797.67
Bottom Layer_L8:
  rectangle: 600,3553.58 1056.69,3797.67
Plane_L2 (plane layer: these items are gaps in the copper):
  pour cut-out: 619.69,3797.67 619.69,3616.57 1033.07,3616.57 1033.07,3797.67

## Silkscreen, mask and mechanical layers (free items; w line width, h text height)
Top Overlay:
  text "There is no copper under the filter" at 650,3852.41 h27.56
  text "Only on the bottom side" at 710,3812.69 h27.56
  text "chip1" at 3200,3153.98 h78.74
  text "chip2" at 2930,3138.98 h78.74
  text "RF SW" at 2610,3135.82 h78.74
Board Layer Stack Bottom Overlay:
  drawing of 14 lines, arcs and shapes, not listed
  text "+12V" at 3375.02,3197.53 h100 r270
  text "GND" at 3650.02,3192.53 h100 r270
  text "Quantum Source Labs LTD." at 3710.02,1532.53 h100
  text "Board P/N: ______________" at 3705.02,1437.53 h100
  text "S/N:____________________" at 3705.02,1342.53 h100
  text "Apr. 2023" at 3710.52,1223.82 h100
Board:
  lines w1: 30.01,3475.78 ccw(c30.02,3445.25) 1.68,3433.89 ccw(c30.02,3422.53) -0.51,3422.53 -0.51,177.53 ccw(c30.02,177.53) 30.02,147 619.57,147 ccw(c619.57,178.05) 650.61,178.05 650.61,432.04 1310.96,432.04 1310.96,138.28 ccw(c1342.01,138.28) 1342.01,107.24 1627.63,107.24 ccw(c1627.63,138.28) 1658.67,138.28 1658.66,138.36 1658.66,391.24 cw(c1729.39,391.24) 1665.05,420.6 1665.72,420.87 cw(c1729.39,392.09) 1729.39,461.96 1729.4,461.96 cw(c1729.4,391.24) 1800.12,391.24 1800.12,20.35 1800.68,19.38 1820.63,-0.36 1821.35,-0.66 2224.05,-0.66 2224.78,-0.36 2244.61,19.47 2244.91,20.2 2244.91,322.18 cw(c2276.2,322.18) 2276.2,353.47 2283.83,353.47 cw(c2283.83,322.33) 2314.97,322.33 2314.97,20.57 2316,19.54 3108.65,19.54 ccw(c3120.65,47.61) 3132.64,19.54 3150.65,19.54 3151.68,20.57 3151.68,429.87 3967.02,429.87 ccw(c3967.02,460.4) 3997.55,460.41 3997.55,3422.53 ; 30.02,3475.78 3967.02,3475.78 cw(c3967.02,3445.25) 3997.55,3445.25 ; 30.01,3475.78 30.02,3475.78 ; 3997.55,3422.54 ccw(c3967.02,3422.53) 3995.36,3433.89 ccw(c3967.02,3445.25) 3997.55,3445.24 ; 3997.55,3422.54 3997.55,3422.53 ; 3997.55,3445.24 3997.55,3445.25
FAB_DWG_INFO:
  circle w1: c2785.67,-976.02 r8.54
  circle w1: c2760.67,-891.02 r8.54
  pour cut-out: 2928.43,-971.28 2916.68,-1001.91 3014.45,-1021.86 2928.43,-971.28
  pour cut-out: 2499.55,-917.89 2500.57,-885.1 2401.68,-898.43 2499.55,-917.89
  pour cut-out: 2500.11,-1187.61 2500.11,-1220.42 2401.68,-1204.01 2500.11,-1187.61
  pour cut-out: 2233.57,-1187.61 2233.57,-1220.42 2332,-1204.01 2233.57,-1187.61
  pour cut-out: 1821.38,-2382.78 1854.19,-2382.78 1837.78,-2481.21 1821.38,-2382.78
  pour cut-out: 1821.38,-2650.89 1854.19,-2650.89 1837.78,-2552.47 1821.38,-2650.89
  lines w1: 1023.85,-1204.01 2233.57,-1204.01 ; 1208.85,-2748.32 1837.78,-2748.32 ; 1788.57,-2552.47 2337.31,-2552.47 ; 1788.57,-2481.21 2307.39,-2481.21 ; 1837.78,-2749.32 1837.78,-2650.89 ; 1837.78,-2552.47 1837.78,-2481.21 ; 1837.78,-2382.78 1837.78,-2284.36 ; 2332,-1253.22 2332,-1065.52 ; 2332,-1204.01 2401.68,-1204.01 ; 2332,-1040.91 2332,-2481.21 2361.92,-2552.47 2371.76,-2552.47 2401.68,-2481.21 2401.68,-1040.91 ; 2366.84,-2542.02 2366.84,-2394.6 ; 2366.84,-2383.02 2366.84,-2286.02 ; 2366.84,-2274.02 2366.84,-2227.02 ; 2366.84,-2217.02 2366.84,-2069.6 ; 2366.84,-2058.02 2366.84,-1961.02 ; 2366.84,-1949.02 2366.84,-1902.02 ; 2366.84,-1892.02 2366.84,-1744.6 ; 2366.84,-1733.02 2366.84,-1636.02 ; 2366.84,-1624.02 2366.84,-1577.02 ; 2366.84,-1567.02 2366.84,-1419.6 ; 2366.84,-1408.02 2366.84,-1311.02 ; 2366.84,-1299.02 2366.84,-1252.02 ; 2366.84,-1242.02 2366.84,-1094.6 ; 2366.84,-1083.02 2366.84,-986.02 ; 2366.84,-974.02 2366.84,-927.02 ; 2366.84,-917.02 2366.84,-769.6 ; 2401.68,-1253.22 2401.68,-1065.52 ; 2401.68,-1016.31 2401.68,-849.22 ; 2414.08,-2451.69 2517,-2206.56 2526.53,-2183.87 3033.5,-976.49 ; 2500.06,-901.49 cw(c2401.68,-2481.21) 2546.89,-905.11 ; 2500.11,-1204.01 2598.53,-1204.01 ; 2881.54,-972.93 cw(c2401.68,-2481.21) 2922.55,-986.6
  lines w5: 1598.92,-3154.29 3058.92,-3154.29 ; 1598.92,-3144.29 3058.92,-3144.29
  text "There is no copper under the filter" at 460.79,4090.75 h39.37
  text "Only on the bottom side" at 586.77,4008.08 h39.37
  text "There is no copper under the filter" at 752.32,3980.2 h39.37
  text "There is no copper under the filter" at 350.79,3952.84 h39.37
  text "Only on the bottom side" at 476.77,3870.16 h39.37
  text "General Notes for PCB production:" at 4645.95,3379.31 h196.85
  text "1. General:" at 4608.87,3182.26 h118.11
  text "1.1 Drill per drilling table on the drill drawing." at 4768.28,3084.27 h118.11
  text "1.2 All holes sizes are after platind." at 4768.28,2985.85 h118.11
  text "1.3 Manufacturing per IPC-6012-A (last version)." at 4768.28,2887.42 h118.11
  text "1.4 General tolerance: +/-0.2mm unless otherwise specified/" at 4768.28,2789 h118.11
  text "1.5 Hole size tolerance: +/-0.1mm +/-0.05mm, unless otherwise specified/" at 4768.28,2690.57 h118.11
  text "1.6 Each production batch/lot should be delivered with a C.O.C. and test report." at 4768.28,2592.15 h118.11
  text "2. Material:" at 4610.8,2493.72 h118.11
  text "2.1 Class epoxy FR4 Total thickness: 1.6 mm +/-10%" at 4768.28,2395.3 h118.11
  text "2.2 Material should be fire resistance and UL-94V-0 recognized." at 4768.28,2296.87 h118.11
  text "2.3.NO. OF LAYERS: 8LAYERS." at 4768.28,2198.45 h118.11
  text "3. Plating:" at 4610.8,2100.02 h118.11
  text "3.1 ROHS complieant immersion gold (gold 0.05um min.+nickel 3um min.) ,HI TG-170." at 4768.28,2001.6 h118.11
  text "3.2 All holes to be plated thru, except noted else." at 4768.28,1903.17 h118.11
  text "4. Solder mask:" at 4610.8,1804.75 h118.11
  text "4.1 Solder mask per IPC-SM-840M." at 4768.28,1706.32 h118.11
  text "4.2 Solder mask type:wet photoimageable class 2, color green on both sides of the board." at 4768.28,1607.9 h118.11
  text "4.3 Solder mask over copper to cover all traces completety." at 4768.28,1509.47 h118.11
  text "5. Marking:" at 4615.8,1397.62 h118.11
  text "5.1 All the markings on the board should be with proxy ink, both sides unless otherwise." at 4773.28,1299.2 h118.11
  text "5.2 Board to be marked with manufacturing code which mets U.L.  flammability rating 94V-0, or better." at 4773.28,1200.77 h118.11
  text "5.3 E.S.D. symbol to be marked with yellow / white epoxy ink." at 4773.28,1102.35 h118.11
  text "6. Final test:" at 4615.8,1003.92 h118.11
  text "6.1 Each board to be visual and mechanical tested per IPC-A-600 class 2 workmanship standart." at 4773.28,905.49 h118.11
  text "6.2 Bow and twist per IPC-TM-650 wrap age shall not exceed 0.75%," at 4773.28,807.07 h118.11
  text "each board must be measured on each corner." at 4989.81,708.64 h118.11
  text "DETAIL A" at 3700.74,141.82 h125
  text "20" at 2668.67,-949.02 h50
  text "+/- 5" at 2632.56,-1015.75 h31
  text "1.57" at 1038.67,-1162.02 h50
  text "MAX OVER PLATING" at 1286.74,-1165.23 h50
  text "0.062" at 1122.17,-1345.52 h50
  text "[" at 1049.82,-1370.55 h125
  text "]" at 1332.56,-1372.28 h125
  text "+0,25" at 917.56,-2525.75 h31
  text "1,3" at 669.67,-2578.02 h50
  text "-0,25" at 917.56,-2614.33 h31
  text "+,010" at 921.71,-2742.28 h31
  text "0,051" at 628.67,-2795.02 h50
  text "-,010" at 921.71,-2830.87 h31
  text "[" at 536.85,-2833.99 h125
  text "]" at 1093.93,-2833.99 h125
  text "DETAIL A" at 1593.92,-3104.29 h125
FAB:
  lines w10: 8079.29,473.91 8079.29,4372.91

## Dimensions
29.02,256.27 to 3967.02,3475.78 on FAB_DWG_INFO
29.02,335.01 to 3997.55,3422.54 on FAB_DWG_INFO
29.02,295.64 to 3997.55,3422.53 on FAB_DWG_INFO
